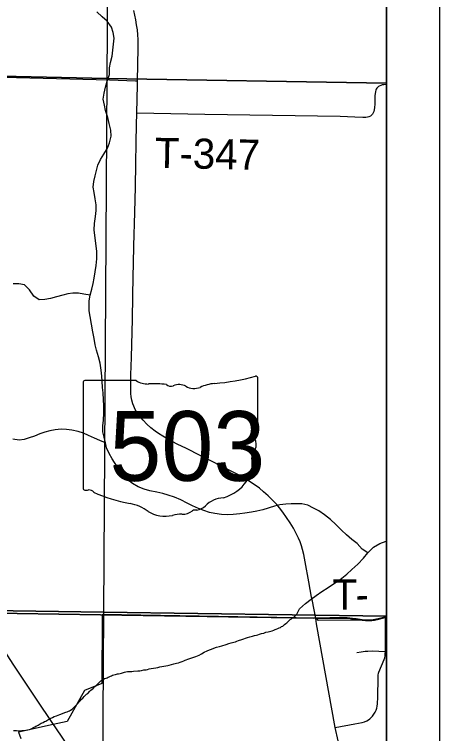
# Model space of a CAD drawing. Extents: x -8.8 to 41.4, y 0 to 34.6.
# Drawn here: x -2.577 to -1.774, y 18.37 to 19.729 of the extents above; entities that cross this region are included whole.
import ezdxf

# ---------------------------------------------------------------- set-up
doc = ezdxf.new("R2010")
doc.units = 0
for name, color, linetype in [('GM_X_City_Street', 7, 'Continuous'), ('GM_X_Corporation', 7, 'Continuous'), ('GM_X_Minor_River', 7, 'Continuous'), ('GM_X_Section_Text', 7, 'Continuous'), ('GM_X_State_Route', 7, 'Continuous'), ('GM_X_Township_Road', 7, 'Continuous'), ('GM_X_Unincorporated_Location', 7, 'Continuous'), ('SH_Border', 7, 'Continuous')]:
    doc.layers.add(name, color=color, linetype=linetype)

msp = doc.modelspace()

# ---------------------------------------------------------------- linework, layer by layer
at = {"layer": 'GM_X_City_Street'}
for p, q in [((-2.1177, 18.9376), (-2.1177, 19.0423)), ((-2.4473, 19.0339), (-2.4473, 18.8337)), ((-2.3475, 19.0373), (-2.444, 19.0373)), ((-2.1177, 18.9376), (-2.1177, 18.9376))]:
    msp.add_line(p, q, dxfattribs=at)
for points in [[(-1.9715, 18.3821), (-1.9341, 18.3888), (-1.9207, 18.3913), (-1.9159, 18.3926), (-1.912, 18.3944), (-1.9088, 18.3962), (-1.9063, 18.3982), (-1.9035, 18.4007), (-1.901, 18.4034), (-1.8983, 18.4069), (-1.8961, 18.4107), (-1.8943, 18.4146), (-1.893, 18.4182), (-1.8921, 18.4223), (-1.8916, 18.4267), (-1.891, 18.439), (-1.8906, 18.4766), (-1.8903, 18.481), (-1.8899, 18.4842), (-1.8891, 18.4863), (-1.8789, 18.5106), (-1.8776, 18.5136), (-1.877, 18.5172), (-1.8768, 18.5208), (-1.8767, 18.5255), (-1.8763, 18.5899)], [(-1.9308, 18.5236), (-1.9222, 18.5249), (-1.9148, 18.5259), (-1.9099, 18.5263), (-1.9018, 18.5264), (-1.8767, 18.5255)]]:
    msp.add_lwpolyline(points, dxfattribs=at)
for centre, major_axis, start_param, end_param in [((-2.2351, 19.3101), (0.3495, 0), 4.814394, 5.042369), ((-2.1213, 19.0427), (0.00367, 0), 6.141152, 7.989035), ((-2.4435, 19.0343), (0.00382, 0), 1.712693, 3.28349), ((-2.3245, 19.0605), (0.037, 0), 4.042523, 4.731795), ((-2.3122, 18.925), (0.133, 0), 1.404758, 1.657858), ((-2.282, 19.0353), (0.0107, 0), 3.836095, 5.185415), ((-2.2664, 19.0122), (0.0222, 0), 0.950623, 2.079405), ((-2.1905, 18.9762), (0.0703, 0), 1.699011, 2.107814), ((-2.2377, 19.0439), (0.0267, 0), 4.081561, 5.145723), ((-2.1185, 18.9299), (0.00568, 0), 1.883978, 3.671073), ((-2.1216, 18.9372), (0.00393, 0), 5.05454, 6.418171), ((-2.1546, 18.9167), (0.0341, 0), 5.934695, 6.695948), ((-2.1045, 18.8938), (0.0248, 0), 2.387724, 3.262537), ((-2.2155, 18.8805), (0.0874, 0), 5.101752, 6.440018), ((-2.4434, 18.8333), (0.00385, 0), 3.00124, 4.508301), ((-2.4429, 18.8538), (0.0294, 0), 4.665946, 4.897461), ((-2.4368, 18.8222), (0.0106, 0), 0.519207, 1.627899), ((-2.303, 19.002), (0.2524, 0), 4.195997, 4.488961), ((-2.1786, 18.7776), (0.0479, 0), 1.647645, 2.488434), ((-2.3783, 18.7438), (0.079, 0), 0.823519, 1.323587), ((-2.2393, 18.8143), (0.0282, 0), 4.937069, 5.64225), ((-2.2929, 18.8212), (0.0501, 0), 4.026481, 4.996735), ((-2.2639, 18.752), (0.0412, 0), 1.495662, 1.94098), ((-2.2602, 18.8062), (0.0267, 0), 4.691044, 5.507374), ((-2.2361, 18.7868), (0.00752, 0), 1.147584, 2.315152)]:
    msp.add_ellipse(centre, major_axis=major_axis, ratio=0.8, start_param=start_param, end_param=end_param, dxfattribs=at)
at = {"layer": 'GM_X_Corporation'}
for points in [[(-3.8955, 18.6215), (-2.6721, 18.5991), (-2.6516, 18.5988), (-2.415, 18.595), (-2.0117, 18.5884), (-1.9817, 18.589), (-1.9577, 18.5892), (-1.9489, 18.5889), (-1.9385, 18.5879), (-1.9317, 18.587), (-1.9207, 18.5853), (-1.9111, 18.5843), (-1.9085, 18.5843), (-1.9028, 18.5846), (-1.8976, 18.5853), (-1.8801, 18.5896), (-1.8743, 18.5906), (-1.8743, 20.9), (-5.3683, 20.9)], [(-1.8743, 14.1), (-1.8743, 18.5906), (-1.8801, 18.5896), (-1.8976, 18.5853), (-1.9028, 18.5846), (-1.9085, 18.5843), (-1.9111, 18.5843), (-1.9207, 18.5853), (-1.9317, 18.587), (-1.9385, 18.5879), (-1.9489, 18.5889), (-1.9577, 18.5892), (-1.9817, 18.589), (-2.0117, 18.5884), (-2.415, 18.595), (-2.6516, 18.5988), (-2.6721, 18.5991), (-3.8955, 18.6215)], [(-1.8743, 17.5032), (-1.8743, 18.5904), (-1.8766, 18.5904), (-1.8801, 18.5896), (-1.8841, 18.5886), (-1.8999, 18.585), (-1.9179, 18.5849), (-1.9406, 18.5847), (-2.0037, 18.5837), (-2.0085, 18.5883), (-2.4118, 18.5951), (-2.4118, 18.5922), (-2.4123, 18.4649), (-2.4446, 18.4517), (-2.4778, 18.3932), (-2.5041, 18.3877), (-2.5697, 18.3731), (-2.565, 18.3613)]]:
    msp.add_lwpolyline(points, dxfattribs=at)
for points in [[(-3.3926, 20.6407), (-2.3956, 20.6214), (-2.4029, 19.6082), (-3.4024, 19.6303)], [(-1.8743, 19.5991), (-1.8743, 20.6135), (-2.3956, 20.6214), (-2.4029, 19.6082)], [(-2.4029, 19.6082), (-2.4092, 18.5999), (-3.3893, 18.614), (-3.4272, 18.6145), (-3.4024, 19.6303)], [(-1.8743, 18.5922), (-1.8743, 19.5991), (-2.4029, 19.6082), (-2.4092, 18.5999)], [(-3.3893, 18.614), (-2.4092, 18.5999), (-2.4162, 17.5144), (-3.4102, 17.5315)], [(-1.8743, 17.5082), (-1.8743, 18.5922), (-2.4092, 18.5999), (-2.4162, 17.5144)]]:
    msp.add_lwpolyline(points, close=True, dxfattribs=at)
at = {"layer": 'GM_X_Minor_River'}
for points in [[(-2.405, 19.548), (-2.4074, 19.5576), (-2.4099, 19.569), (-2.4078, 19.5804), (-2.4053, 19.5921), (-2.4024, 19.6034), (-2.3976, 19.6158), (-2.3974, 19.6283), (-2.3961, 19.6382), (-2.3928, 19.6506), (-2.3911, 19.6616), (-2.3901, 19.673), (-2.3892, 19.6847), (-2.3905, 19.6954), (-2.3941, 19.7053), (-2.4018, 19.7168), (-2.4116, 19.725), (-2.4216, 19.7339)], [(-1.91, 18.7116), (-1.9205, 18.719), (-1.9298, 18.7294), (-1.9399, 18.7372), (-1.95, 18.7461), (-1.9597, 18.755), (-1.9701, 18.7654), (-1.9806, 18.7747), (-1.9918, 18.7837), (-2.0023, 18.7911), (-2.0124, 18.7965), (-2.0233, 18.8017), (-2.0343, 18.8045), (-2.0445, 18.8044), (-2.0544, 18.8045), (-2.0647, 18.804), (-2.0761, 18.8023), (-2.0864, 18.7998), (-2.1081, 18.793), (-2.1192, 18.7906), (-2.1298, 18.7885), (-2.142, 18.7868), (-2.1515, 18.7855), (-2.164, 18.7842), (-2.1743, 18.784), (-2.186, 18.7846), (-2.1989, 18.786), (-2.2087, 18.7884), (-2.2193, 18.792), (-2.2295, 18.7957), (-2.2408, 18.8004), (-2.2513, 18.8059), (-2.2629, 18.8118), (-2.275, 18.817), (-2.2871, 18.821), (-2.2969, 18.8238), (-2.3086, 18.8263), (-2.3214, 18.8288), (-2.3324, 18.8321), (-2.3437, 18.8368), (-2.3542, 18.8427), (-2.3654, 18.852), (-2.3751, 18.8628), (-2.3828, 18.874), (-2.3928, 18.8897), (-2.3983, 18.8993), (-2.4034, 18.91), (-2.4055, 18.9195), (-2.408, 18.9306), (-2.4101, 18.9408), (-2.4102, 18.9518), (-2.4093, 18.9624), (-2.4083, 18.9757), (-2.4084, 18.9901), (-2.409, 19.0011), (-2.4098, 19.0144), (-2.4108, 19.0243), (-2.4117, 19.0361), (-2.4123, 19.0456), (-2.4132, 19.057), (-2.4156, 19.0703), (-2.4185, 19.0825), (-2.422, 19.0947), (-2.4245, 19.105), (-2.4269, 19.1171), (-2.4294, 19.1297), (-2.4345, 19.1582), (-2.4362, 19.1693), (-2.4364, 19.1788), (-2.4362, 19.1882), (-2.4345, 19.1985), (-2.4309, 19.2101), (-2.4284, 19.2211), (-2.4267, 19.2309), (-2.4246, 19.243), (-2.4229, 19.2551), (-2.4215, 19.2676), (-2.4216, 19.282), (-2.4226, 19.2915), (-2.4239, 19.3018), (-2.4252, 19.3117), (-2.4266, 19.3223), (-2.426, 19.3345), (-2.4242, 19.3477), (-2.4229, 19.3587), (-2.423, 19.3693), (-2.4247, 19.3807), (-2.4268, 19.3925), (-2.4285, 19.4028), (-2.4275, 19.4134), (-2.4247, 19.424), (-2.4198, 19.4444), (-2.415, 19.4549), (-2.4084, 19.4654), (-2.4013, 19.4763), (-2.3974, 19.4864), (-2.3945, 19.4993), (-2.395, 19.5107), (-2.3982, 19.5233), (-2.401, 19.5347), (-2.405, 19.548)], [(-2.4345, 19.1985), (-2.4459, 19.2009), (-2.4561, 19.2026), (-2.4667, 19.2028), (-2.4766, 19.2015), (-2.4861, 19.199), (-2.4976, 19.1955), (-2.509, 19.1923), (-2.5197, 19.1906), (-2.5303, 19.19), (-2.5408, 19.197), (-2.5486, 19.2089), (-2.5582, 19.2186), (-2.5692, 19.2203), (-2.5795, 19.2205)], [(-2.4055, 18.9195), (-2.4157, 18.9243), (-2.4258, 18.9286), (-2.4371, 18.9338), (-2.4469, 18.9381), (-2.4571, 18.941), (-2.4688, 18.9435), (-2.4787, 18.9448), (-2.4889, 18.9457), (-2.5003, 18.944), (-2.5102, 18.9423), (-2.5197, 18.9402), (-2.5293, 18.9366), (-2.5392, 18.9326), (-2.5491, 18.929), (-2.5587, 18.9262), (-2.5686, 18.9248), (-2.5803, 18.9266)], [(-2.0441, 18.5957), (-2.0387, 18.6059), (-2.0275, 18.6163), (-2.0171, 18.6241), (-2.0075, 18.6311), (-1.9964, 18.6389), (-1.9848, 18.6463), (-1.9726, 18.6544), (-1.9618, 18.6618), (-1.9498, 18.6718), (-1.9398, 18.6803), (-1.9286, 18.6903), (-1.9178, 18.7015), (-1.91, 18.7116), (-1.8992, 18.7224), (-1.8873, 18.7294), (-1.8755, 18.7341), (-1.8743, 18.7344)], [(-2.3694, 18.4861), (-2.3667, 18.4867), (-2.3636, 18.4874), (-2.3594, 18.4876), (-2.3556, 18.4879), (-2.3522, 18.4881), (-2.3439, 18.4886), (-2.3404, 18.4892), (-2.3374, 18.4895), (-2.3328, 18.4908), (-2.3286, 18.4911), (-2.3259, 18.4917), (-2.3225, 18.4924), (-2.3187, 18.4934), (-2.3145, 18.494), (-2.3103, 18.4946), (-2.3065, 18.4952), (-2.3027, 18.4962), (-2.2989, 18.4968), (-2.2954, 18.4979), (-2.2912, 18.4985), (-2.2878, 18.4991), (-2.2851, 18.4998), (-2.2809, 18.5008), (-2.2759, 18.5021), (-2.271, 18.5031), (-2.2671, 18.5041), (-2.2641, 18.5051), (-2.2606, 18.5065), (-2.2575, 18.5079), (-2.2548, 18.5089), (-2.2479, 18.5117), (-2.2345, 18.5158), (-2.2283, 18.5187), (-2.2241, 18.5212), (-2.2187, 18.5244), (-2.2133, 18.5265), (-2.2087, 18.5286), (-2.2048, 18.53), (-2.2006, 18.5317), (-2.1956, 18.5335), (-2.1899, 18.5351), (-2.1857, 18.5361), (-2.1772, 18.5389), (-2.1726, 18.5406), (-2.168, 18.542), (-2.1631, 18.5429), (-2.16, 18.544), (-2.1573, 18.545), (-2.1539, 18.546), (-2.1477, 18.5481), (-2.1443, 18.5491), (-2.1408, 18.5505), (-2.137, 18.5519), (-2.1324, 18.5532), (-2.1278, 18.5546), (-2.1236, 18.5556), (-2.1201, 18.5562), (-2.1175, 18.5569), (-2.1144, 18.5579), (-2.1109, 18.5593), (-2.1064, 18.5603), (-2.1025, 18.5617), (-2.0983, 18.5627), (-2.0907, 18.5647), (-2.0872, 18.5657), (-2.0849, 18.5667), (-2.083, 18.5674), (-2.0799, 18.5689), (-2.0772, 18.5699), (-2.0749, 18.571), (-2.0726, 18.5724), (-2.0703, 18.5735), (-2.0671, 18.5764), (-2.0648, 18.5782), (-2.0628, 18.5797), (-2.0562, 18.5859), (-2.0542, 18.5873), (-2.0515, 18.5895), (-2.0492, 18.5906), (-2.046, 18.5939), (-2.0441, 18.5957)], [(-2.579, 18.3764), (-2.5764, 18.3763), (-2.5733, 18.3762), (-2.5703, 18.3757), (-2.5669, 18.3756), (-2.5635, 18.3759), (-2.5604, 18.3761), (-2.5521, 18.3773), (-2.549, 18.378), (-2.5471, 18.3787), (-2.539, 18.383), (-2.5367, 18.3844), (-2.5347, 18.3851), (-2.5324, 18.3862), (-2.5305, 18.3876), (-2.5266, 18.3897), (-2.5231, 18.3915), (-2.5204, 18.3929), (-2.5181, 18.394), (-2.5162, 18.3951), (-2.5143, 18.3965), (-2.5119, 18.3976), (-2.5085, 18.3994), (-2.5054, 18.4008), (-2.5019, 18.4026), (-2.4981, 18.4039), (-2.4946, 18.405), (-2.4912, 18.4064), (-2.4804, 18.4105), (-2.4777, 18.4116), (-2.4754, 18.4126), (-2.4731, 18.4133), (-2.4712, 18.4148), (-2.4684, 18.4166), (-2.4661, 18.4184), (-2.4638, 18.4206), (-2.4582, 18.4265), (-2.4555, 18.4298), (-2.4531, 18.4324), (-2.4507, 18.4353), (-2.448, 18.4375), (-2.4456, 18.4405), (-2.4433, 18.4427), (-2.4409, 18.4445), (-2.4386, 18.4463), (-2.4347, 18.4504), (-2.4327, 18.4526), (-2.4303, 18.4544), (-2.4284, 18.4558), (-2.4253, 18.4592), (-2.4229, 18.4614), (-2.421, 18.4628), (-2.4178, 18.4665), (-2.4158, 18.4683), (-2.4139, 18.4698), (-2.4116, 18.4712), (-2.4096, 18.4727), (-2.4073, 18.4741), (-2.4042, 18.4752), (-2.4023, 18.4758), (-2.4004, 18.4769), (-2.3985, 18.4776), (-2.3961, 18.4787), (-2.3942, 18.4794), (-2.3919, 18.4804), (-2.3896, 18.4811), (-2.3866, 18.4817), (-2.3846, 18.4824), (-2.3823, 18.4831), (-2.3804, 18.4834), (-2.3778, 18.4837), (-2.3751, 18.4844), (-2.3732, 18.4851), (-2.3694, 18.4861)]]:
    msp.add_lwpolyline(points, dxfattribs=at)
at = {"layer": 'GM_X_State_Route'}
for p, q in [((-2.0065, 18.5779), (-2.0083, 18.5878)), ((-2.5067, 18.3914), (-2.5039, 18.3872)), ((-2.5039, 18.3872), (-2.5011, 18.383))]:
    msp.add_line(p, q, dxfattribs=at)
for points in [[(-2.0161, 18.6282), (-2.0212, 18.6571), (-2.0282, 18.695), (-2.031, 18.709), (-2.0331, 18.7181), (-2.0353, 18.7253), (-2.0378, 18.7324), (-2.0409, 18.7399), (-2.0456, 18.7494), (-2.0503, 18.7582), (-2.0568, 18.7688), (-2.0633, 18.7787), (-2.0705, 18.7889), (-2.0766, 18.7968), (-2.0819, 18.8029), (-2.0887, 18.8102), (-2.0981, 18.8194), (-2.1068, 18.8273), (-2.1145, 18.8338), (-2.1224, 18.8397), (-2.1312, 18.8457), (-2.1418, 18.8522), (-2.1527, 18.8584), (-2.1653, 18.865), (-2.2263, 18.8958), (-2.2524, 18.9089), (-2.2697, 18.9175), (-2.2851, 18.9255), (-2.2969, 18.9321), (-2.3052, 18.9375), (-2.3112, 18.9418), (-2.3194, 18.9483), (-2.3272, 18.9553), (-2.3342, 18.9623), (-2.3387, 18.9673), (-2.3432, 18.9731), (-2.3456, 18.9767), (-2.3493, 18.983), (-2.352, 18.9892), (-2.3535, 18.9932), (-2.3555, 19.0003), (-2.3566, 19.0069), (-2.3572, 19.0131), (-2.3576, 19.0217), (-2.3575, 19.031), (-2.3572, 19.0484), (-2.3563, 19.0813), (-2.3545, 19.1534), (-2.3537, 19.1968), (-2.3529, 19.2341), (-2.3523, 19.2589), (-2.3515, 19.2918), (-2.3501, 19.3552), (-2.3489, 19.4036), (-2.348, 19.4471), (-2.3473, 19.4875), (-2.3464, 19.5204), (-2.3461, 19.5426), (-2.3448, 19.5965), (-2.3447, 19.6039), (-2.3437, 19.6655), (-2.3438, 19.6817), (-2.3442, 19.691), (-2.345, 19.7003), (-2.3464, 19.7096), (-2.3481, 19.7188), (-2.352, 19.737)], [(-2.0083, 18.5878), (-2.0152, 18.6234), (-2.0161, 18.6282)], [(-2.6484, 18.6001), (-2.6204, 18.5613), (-2.6079, 18.5435), (-2.5801, 18.5016), (-2.5674, 18.4824), (-2.5348, 18.4332), (-2.5067, 18.3914)], [(-1.9445, 18.0517), (-1.9442, 18.1144), (-1.9448, 18.1873), (-1.9453, 18.2838), (-1.9449, 18.2892), (-1.9446, 18.2932), (-1.9441, 18.298), (-1.9615, 18.3416), (-1.9638, 18.3477), (-1.9651, 18.3521), (-1.9661, 18.3564), (-1.9715, 18.3821), (-2.0065, 18.5779)], [(-2.5011, 18.383), (-2.4697, 18.3362), (-2.4397, 18.2967), (-2.4308, 18.2864), (-2.4219, 18.2769), (-2.4114, 18.2664), (-2.401, 18.2567), (-2.3875, 18.2448), (-2.3784, 18.2373), (-2.3681, 18.2293), (-2.357, 18.2214), (-2.3446, 18.2132), (-2.3358, 18.2078), (-2.3314, 18.2051), (-2.3174, 18.197), (-2.3043, 18.19), (-2.2932, 18.1845), (-2.2802, 18.1787), (-2.2664, 18.173), (-2.253, 18.168), (-2.2425, 18.1645), (-2.2252, 18.1593), (-2.2098, 18.1551)]]:
    msp.add_lwpolyline(points, dxfattribs=at)
at = {"layer": 'GM_X_Township_Road'}
for points in [[(-3.4948, 19.6264), (-3.4861, 19.6272), (-3.4793, 19.6279), (-3.4718, 19.6281), (-3.3693, 19.6264), (-3.306, 19.6254), (-3.224, 19.6246), (-3.165, 19.6234), (-3.1054, 19.6216), (-2.9893, 19.6199), (-2.8701, 19.6174), (-2.7502, 19.6145), (-2.5229, 19.609), (-2.3975, 19.6058), (-2.3814, 19.6052), (-2.3486, 19.604), (-2.3447, 19.6039)], [(-1.8743, 19.5969), (-1.8759, 19.5968), (-1.8798, 19.5964), (-1.8827, 19.596), (-1.8856, 19.5951), (-1.8882, 19.594), (-1.89, 19.5928), (-1.8916, 19.5913), (-1.8927, 19.5899), (-1.8938, 19.5882), (-1.8946, 19.5863), (-1.8955, 19.5835), (-1.896, 19.5794), (-1.8964, 19.576), (-1.8968, 19.5599), (-1.8972, 19.5531), (-1.8978, 19.5491), (-1.8986, 19.5458), (-1.8995, 19.5435), (-1.9013, 19.5406), (-1.9028, 19.5387), (-1.9049, 19.5371), (-1.9079, 19.5357), (-1.9102, 19.5351), (-1.9134, 19.5347), (-1.919, 19.5346), (-1.9346, 19.5354), (-1.9619, 19.5363), (-2.2178, 19.5404), (-2.3461, 19.5426)], [(-2.0083, 18.5878), (-1.9815, 18.5885), (-1.9685, 18.5887), (-1.9575, 18.5887), (-1.9486, 18.5883), (-1.9383, 18.5874), (-1.9314, 18.5865), (-1.9205, 18.5847), (-1.9174, 18.5844), (-1.9144, 18.584), (-1.9109, 18.5837), (-1.9082, 18.5838), (-1.9026, 18.5841), (-1.9, 18.5844), (-1.8973, 18.5848), (-1.8917, 18.586), (-1.8799, 18.5891), (-1.8763, 18.5899), (-1.8743, 18.5901)]]:
    msp.add_lwpolyline(points, dxfattribs=at)
at = {"layer": 'SH_Border'}
for p, q in [((-1.7743, 21), (-1.7743, 14)), ((-1.8743, 20.9), (-1.8743, 14.1))]:
    msp.add_line(p, q, dxfattribs=at)

# ---------------------------------------------------------------- texts
at = {"layer": 'GM_X_City_Street'}
msp.add_text('503', height=0.13184, dxfattribs=at).set_placement((-2.3978, 18.8479))
at = {"layer": 'GM_X_Section_Text'}
for s, height, rotation, p in [('T-347', 0.05682, 358.8773, (-2.3125, 19.4395)), ('T', 0.0568, 359.8988, (-1.9765, 18.6048)), ('-', 0.0568, 1.2214, (-1.9327, 18.6047))]:
    msp.add_text(s, height=height, rotation=rotation, dxfattribs=at).set_placement(p)
at = {"layer": 'GM_X_Unincorporated_Location'}
for s in ['s', 'r']:
    msp.add_text(s, height=0.000189, dxfattribs=at).set_placement((-2.2862, 18.9205))
msp.add_text('503', height=0.000189, rotation=0, dxfattribs=at).set_placement((-2.353, 18.9067))

doc.saveas('drawing.dxf')
